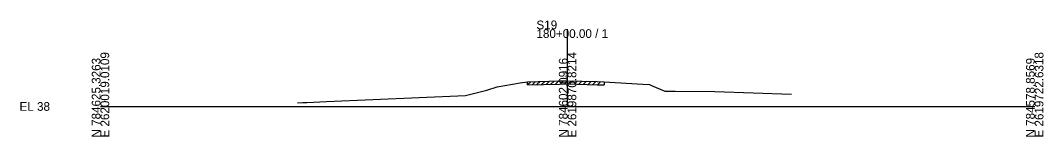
# Model space of a CAD drawing. Extents: x -26 to 1603, y -10 to 5028.
# Drawn here: x -25.7 to 302.8, y 4990.3 to 5027.7 of the extents above; entities that cross this region are included whole.
import ezdxf

# ---------------------------------------------------------------- set-up
doc = ezdxf.new("R2010")
doc.units = 0
for name, color, linetype in [('RD_GPK_XS_Cell', 7, 'Continuous'), ('RD_XS_ExGround', 7, 'Continuous'), ('RD_XS_ExPaveRet', 7, 'Continuous'), ('RD_XS_TX_Elev_EX', 7, 'Continuous')]:
    doc.layers.add(name, color=color, linetype=linetype)

msp = doc.modelspace()

# ---------------------------------------------------------------- linework, layer by layer
at = {"layer": 'RD_GPK_XS_Cell'}
for p, q in [((150, 5000), (150, 5024.84)), ((0, 5000), (150, 5000)), ((150, 5000), (300, 5000))]:
    msp.add_line(p, q, dxfattribs=at)
at = {"layer": 'RD_XS_ExGround'}
for p, q in [((127.4, 5006.33), (134.76, 5007.56)), ((134.76, 5007.56), (137.15, 5007.94)), ((137.15, 5007.94), (147.45, 5008.2)), ((147.45, 5008.2), (149.95, 5008.28)), ((149.95, 5008.28), (159.49, 5007.99)), ((159.49, 5007.99), (161.72, 5007.93)), ((161.72, 5007.93), (174.21, 5007.22)), ((174.21, 5007.22), (176.26, 5007.07)), ((176.26, 5007.07), (176.95, 5006.77)), ((117.23, 5003.54), (124.04, 5005.29)), ((124.04, 5005.29), (127.4, 5006.33)), ((176.95, 5006.77), (181.23, 5004.94)), ((181.23, 5004.94), (182.96, 5004.92)), ((182.96, 5004.92), (184.57, 5004.9)), ((184.57, 5004.9), (197.27, 5004.76)), ((197.27, 5004.76), (221.95, 5003.94)), ((63.25, 5001.15), (64.93, 5001.22)), ((64.93, 5001.22), (66.32, 5001.28)), ((66.32, 5001.28), (72.61, 5001.56)), ((72.61, 5001.56), (117.23, 5003.54))]:
    msp.add_line(p, q, dxfattribs=at)
at = {"layer": 'RD_XS_ExPaveRet'}
for p, q in [((137.15, 5006.94), (138.18, 5007.96)), ((137.15, 5006.94), (137.15, 5007.94)), ((137.15, 5006.94), (147.45, 5007.2)), ((138.65, 5006.98), (139.68, 5008)), ((140.15, 5007.01), (141.18, 5008.04)), ((141.65, 5007.05), (142.68, 5008.08)), ((143.15, 5007.09), (144.18, 5008.12)), ((144.65, 5007.13), (145.68, 5008.16)), ((146.15, 5007.17), (147.18, 5008.2)), ((147.45, 5007.2), (149.95, 5007.28)), ((147.65, 5007.21), (148.68, 5008.24)), ((149.15, 5007.26), (150.17, 5008.27)), ((149.95, 5007.28), (159.49, 5006.99)), ((150.65, 5007.26), (151.62, 5008.23)), ((152.15, 5007.21), (153.12, 5008.18)), ((153.65, 5007.17), (154.62, 5008.14)), ((155.15, 5007.12), (156.12, 5008.09)), ((156.65, 5007.08), (157.62, 5008.05)), ((158.15, 5007.03), (159.12, 5008)), ((159.49, 5006.99), (161.72, 5006.93)), ((159.65, 5006.99), (160.62, 5007.96)), ((161.72, 5007.93), (161.72, 5006.93))]:
    msp.add_line(p, q, dxfattribs=at)

# ---------------------------------------------------------------- texts
at = {"layer": 'RD_GPK_XS_Cell'}
for s, p in [('S19', (140, 5024.84)), ('180+00.00 / 1', (140, 5022.04)), ('EL 38', (-26, 4998.6))]:
    msp.add_text(s, height=2.8, dxfattribs=at).set_placement(p)
for s, p in [('E 2620019.0109', (2.8, 4990)), ('E 2619870.8214', (152.8, 4990)), ('E 2619722.6318', (302.8, 4990)), ('N 784625.3263', (0, 4990)), ('N 784602.0916', (150, 4990)), ('N 784578.8569', (300, 4990))]:
    msp.add_text(s, height=2.8, rotation=90, dxfattribs=at).set_placement(p)
at = {"layer": 'RD_XS_TX_Elev_EX'}
msp.add_text('46.28', height=0.8, rotation=90, dxfattribs=at).set_placement((149.9, 5008.72))

doc.saveas('drawing.dxf')
